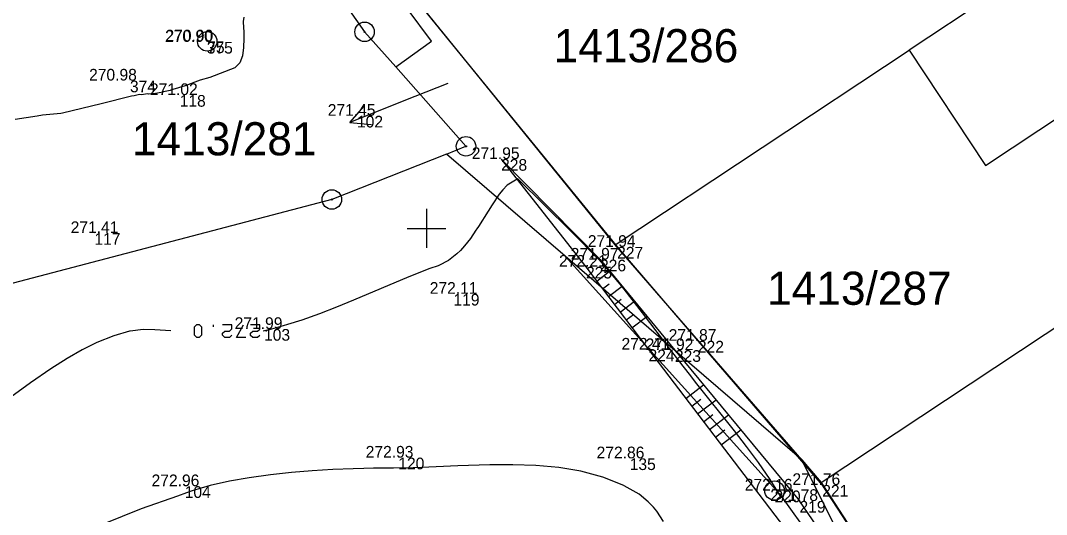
# Model space of a CAD drawing. Extents: x -771260 to -770828, y -1053564 to -1052811.
# Drawn here: x -770970.9 to -770918.2, y -1053264.7 to -1053239.3 of the extents above; entities that cross this region are included whole.
import ezdxf

# ---------------------------------------------------------------- set-up
doc = ezdxf.new("R2010")
doc.units = 0
for name, color, linetype in [('14_8_2023_krizky', 7, 'Continuous'), ('18_8_2023_plot', 7, 'Continuous'), ('18_8_2023_sachta', 7, 'Continuous'), ('18_8_2023_ter_hrana', 7, 'Continuous'), ('18_8_2023_ter_pata', 7, 'Continuous'), ('18_8_2023_ter_srafa', 7, 'Continuous'), ('18_8_2023_vrstevnice_po_1m', 7, 'Continuous'), ('18_8_2023_zamereny_bod', 7, 'Continuous'), ('18_8_2023_zamereny_bod_cislo', 7, 'Continuous'), ('18_8_2023_zamereny_bod_vyska', 7, 'Continuous'), ('25_3_2019_krizky_JTSK', 7, 'Continuous'), ('25_3_2019_sachta', 7, 'Continuous'), ('25_3_2019_vrstevnice_interval_po_1m', 7, 'Continuous'), ('25_3_2019_zamereny_bod', 7, 'Continuous'), ('25_3_2019_zamereny_bod_cislo', 7, 'Continuous'), ('25_3_2019_zamereny_bod_vyska', 7, 'Continuous'), ('Default', 7, 'Continuous'), ('DKM_Hranice parcel', 7, 'Continuous'), ('DKM_Parcelní čísla', 7, 'Continuous'), ('DKM_Pop  PČ popisy', 7, 'Continuous'), ('DKM_Značky bodu BP', 7, 'Continuous')]:
    doc.layers.add(name, color=color, linetype=linetype)

# ---------------------------------------------------------------- blocks, each defined once
blk = doc.blocks.new('6.200_1')
at = {"layer": '25_3_2019_sachta'}
blk.add_circle((0, 0), 10, dxfattribs=at)
blk = doc.blocks.new('POINT_DISPLAY')
at = {"layer": 'Default'}
blk.add_line((0, 0), (0, 0), dxfattribs=at)
blk = doc.blocks.new('KRIZEK')
at = {"layer": '25_3_2019_krizky_JTSK'}
for p, q in [((0, 10), (0, -10)), ((-10, 0), (10, 0))]:
    blk.add_line(p, q, dxfattribs=at)

msp = doc.modelspace()

# ---------------------------------------------------------------- linework, layer by layer
at = {"layer": '18_8_2023_plot'}
for p, q in [((-770950.474, -1053238.36), (-770940.208, -1053250.948)), ((-770940.208, -1053250.948), (-770936.059, -1053255.767)), ((-770936.059, -1053255.767), (-770929.672, -1053263.164)), ((-770929.672, -1053263.164), (-770925.377, -1053269.752))]:
    msp.add_line(p, q, dxfattribs=at)
at = {"layer": '18_8_2023_sachta'}
msp.add_circle((-770932.123, -1053263.449), 0.5, dxfattribs=at)
at = {"layer": '18_8_2023_ter_hrana'}
for p, q in [((-770946.168, -1053246.443), (-770941.807, -1053251.969)), ((-770941.807, -1053251.969), (-770938.594, -1053256.22)), ((-770938.594, -1053256.22), (-770931.61, -1053265.367))]:
    msp.add_line(p, q, dxfattribs=at)
at = {"layer": '18_8_2023_ter_pata'}
for p, q in [((-770946.168, -1053246.443), (-770941.087, -1053251.604)), ((-770941.087, -1053251.604), (-770937.24, -1053256.247)), ((-770937.24, -1053256.247), (-770930.841, -1053263.982)), ((-770926.437, -1053270.365), (-770930.841, -1053263.982))]:
    msp.add_line(p, q, dxfattribs=at)
at = {"layer": '18_8_2023_ter_srafa'}
for p, q in [((-770941.254, -1053252.7), (-770940.593, -1053252.2)), ((-770940.952, -1053253.099), (-770940.613, -1053252.842)), ((-770940.651, -1053253.497), (-770939.954, -1053252.971)), ((-770940.349, -1053253.896), (-770939.992, -1053253.626)), ((-770940.048, -1053254.295), (-770939.315, -1053253.741)), ((-770939.746, -1053254.694), (-770939.371, -1053254.41)), ((-770939.445, -1053255.093), (-770938.677, -1053254.512)), ((-770936.68, -1053258.726), (-770935.766, -1053258.028)), ((-770936.376, -1053259.123), (-770935.912, -1053258.768)), ((-770936.073, -1053259.521), (-770935.128, -1053258.799)), ((-770935.77, -1053259.918), (-770935.289, -1053259.551)), ((-770935.466, -1053260.315), (-770934.49, -1053259.57)), ((-770935.163, -1053260.713), (-770934.667, -1053260.334)), ((-770934.859, -1053261.11), (-770933.852, -1053260.341))]:
    msp.add_line(p, q, dxfattribs=at)
at = {"layer": '18_8_2023_vrstevnice_po_1m'}
for points in [[(-770931.787, -1053263.783), (-770932.354, -1053262.878), (-770932.945, -1053262.017), (-770933.555, -1053261.189), (-770934.177, -1053260.384), (-770936.18, -1053257.881), (-770936.422, -1053257.572), (-770936.814, -1053257.07), (-770937.443, -1053256.243), (-770938.896, -1053254.331), (-770939.973, -1053252.963), (-770940.907, -1053251.847), (-770941.026, -1053251.717), (-770941.116, -1053251.619), (-770941.126, -1053251.607), (-770942.592, -1053250.135), (-770945.311, -1053247.458), (-770945.349, -1053247.481), (-770945.848, -1053247.778), (-770946.073, -1053248.015), (-770946.267, -1053248.249), (-770946.629, -1053248.792), (-770946.823, -1053249.116), (-770947.329, -1053249.907), (-770947.416, -1053250.024), (-770947.458, -1053250.087), (-770947.743, -1053250.518), (-770948.044, -1053250.892), (-770948.256, -1053251.129), (-770948.441, -1053251.303), (-770948.872, -1053251.651), (-770949.357, -1053251.9), (-770949.398, -1053251.914), (-770949.821, -1053252.062), (-770950.898, -1053252.48), (-770953.742, -1053253.685), (-770954.618, -1053254.044), (-770955.503, -1053254.387), (-770956.4, -1053254.707), (-770957.14, -1053254.938), (-770957.36, -1053255.006), (-770958.203, -1053255.234), (-770958.256, -1053255.245), (-770958.386, -1053255.273)], [(-770945.848, -1053247.778), (-770945.848, -1053247.778)], [(-770945.311, -1053247.458), (-770945.311, -1053247.458)], [(-770946.267, -1053248.249), (-770946.267, -1053248.249)], [(-770946.073, -1053248.015), (-770946.073, -1053248.015)], [(-770946.629, -1053248.792), (-770946.629, -1053248.792)], [(-770946.823, -1053249.116), (-770946.823, -1053249.116)], [(-770947.329, -1053249.907), (-770947.329, -1053249.907)], [(-770947.416, -1053250.024), (-770947.416, -1053250.024)], [(-770942.592, -1053250.135), (-770942.592, -1053250.135)], [(-770948.044, -1053250.892), (-770948.044, -1053250.892)], [(-770947.743, -1053250.518), (-770947.743, -1053250.518)], [(-770948.441, -1053251.303), (-770948.441, -1053251.303)], [(-770948.256, -1053251.129), (-770948.256, -1053251.129)], [(-770949.357, -1053251.9), (-770949.357, -1053251.9)], [(-770948.872, -1053251.651), (-770948.872, -1053251.651)], [(-770941.126, -1053251.607), (-770941.126, -1053251.607)], [(-770940.907, -1053251.847), (-770940.907, -1053251.847)], [(-770950.898, -1053252.48), (-770950.898, -1053252.48)], [(-770949.821, -1053252.062), (-770949.821, -1053252.062)], [(-770939.973, -1053252.963), (-770939.973, -1053252.963)], [(-770954.618, -1053254.044), (-770954.618, -1053254.044)], [(-770953.742, -1053253.685), (-770953.742, -1053253.685)], [(-770955.503, -1053254.387), (-770955.503, -1053254.387)], [(-770938.896, -1053254.331), (-770938.896, -1053254.331)], [(-770961.677, -1053254.937), (-770961.558, -1053255.047), (-770961.559, -1053255.482), (-770961.679, -1053255.59), (-770961.799, -1053255.59), (-770961.918, -1053255.481), (-770961.917, -1053255.046), (-770961.797, -1053254.937), (-770961.677, -1053254.937)], [(-770960.959, -1053254.939), (-770960.959, -1053255.048)], [(-770960.003, -1053255.486), (-770960.123, -1053255.595), (-770960.362, -1053255.594), (-770960.481, -1053255.485), (-770960.481, -1053255.376), (-770960.361, -1053255.267), (-770960.122, -1053255.268), (-770960.002, -1053255.16), (-770960.001, -1053254.942), (-770960.48, -1053254.941)], [(-770959.285, -1053255.597), (-770959.763, -1053255.595), (-770959.403, -1053254.943)], [(-770958.566, -1053255.49), (-770958.686, -1053255.598), (-770958.925, -1053255.598), (-770959.045, -1053255.489), (-770959.045, -1053255.38), (-770958.925, -1053255.271), (-770958.685, -1053255.272), (-770958.565, -1053255.163), (-770958.565, -1053254.946), (-770959.043, -1053254.944)], [(-770957.36, -1053255.006), (-770957.36, -1053255.006)], [(-770956.4, -1053254.707), (-770956.4, -1053254.707)], [(-770963.135, -1053255.26), (-770963.951, -1053255.204), (-770964.551, -1053255.191), (-770965.22, -1053255.265), (-770965.259, -1053255.276), (-770966.067, -1053255.505), (-770966.931, -1053255.855), (-770967.677, -1053256.223), (-770968.452, -1053256.667), (-770969.289, -1053257.202), (-770970.335, -1053257.926), (-770972.195, -1053259.25), (-770972.396, -1053259.385), (-770972.441, -1053259.413), (-770972.912, -1053259.698), (-770972.947, -1053259.722), (-770973.349, -1053259.992), (-770973.605, -1053260.15), (-770974.329, -1053260.642)], [(-770966.067, -1053255.505), (-770966.067, -1053255.505)], [(-770965.22, -1053255.265), (-770965.22, -1053255.265)], [(-770964.551, -1053255.191), (-770964.551, -1053255.191)], [(-770963.951, -1053255.204), (-770963.951, -1053255.204)], [(-770963.135, -1053255.26), (-770963.135, -1053255.26)], [(-770958.203, -1053255.234), (-770958.203, -1053255.234)], [(-770967.677, -1053256.223), (-770967.677, -1053256.223)], [(-770966.931, -1053255.855), (-770966.931, -1053255.855)], [(-770968.452, -1053256.667), (-770968.452, -1053256.667)], [(-770969.289, -1053257.202), (-770969.289, -1053257.202)], [(-770936.814, -1053257.07), (-770936.814, -1053257.07)], [(-770970.335, -1053257.926), (-770970.335, -1053257.926)], [(-770936.18, -1053257.881), (-770936.18, -1053257.881)], [(-770934.177, -1053260.384), (-770934.177, -1053260.384)], [(-770933.555, -1053261.189), (-770933.555, -1053261.189)], [(-770932.945, -1053262.017), (-770932.945, -1053262.017)], [(-770937.818, -1053265.034), (-770938.172, -1053264.514), (-770938.341, -1053264.296), (-770938.618, -1053264.028), (-770939.069, -1053263.633), (-770939.847, -1053263.198), (-770939.869, -1053263.19), (-770940.941, -1053262.764), (-770942.067, -1053262.462), (-770943.21, -1053262.267), (-770944.376, -1053262.162), (-770945.557, -1053262.123), (-770946.748, -1053262.131), (-770948.381, -1053262.188), (-770950.608, -1053262.285), (-770950.685, -1053262.286), (-770951.699, -1053262.297), (-770951.714, -1053262.297), (-770951.935, -1053262.304), (-770952.726, -1053262.302), (-770953.209, -1053262.319), (-770953.763, -1053262.327), (-770954.809, -1053262.372), (-770955.866, -1053262.436), (-770956.933, -1053262.523), (-770958.014, -1053262.638), (-770959.113, -1053262.788), (-770960.111, -1053262.961), (-770961.108, -1053263.182), (-770962.032, -1053263.457), (-770962.082, -1053263.475), (-770962.326, -1053263.564), (-770962.783, -1053263.731), (-770962.793, -1053263.735), (-770964.655, -1053264.394), (-770966.609, -1053265.169)], [(-770956.933, -1053262.523), (-770956.933, -1053262.523)], [(-770955.866, -1053262.436), (-770955.866, -1053262.436)], [(-770954.809, -1053262.372), (-770954.809, -1053262.372)], [(-770953.763, -1053262.327), (-770953.763, -1053262.327)], [(-770953.209, -1053262.319), (-770953.209, -1053262.319)], [(-770952.726, -1053262.302), (-770952.726, -1053262.302)], [(-770951.935, -1053262.304), (-770951.935, -1053262.304)], [(-770951.699, -1053262.297), (-770951.699, -1053262.297)], [(-770950.608, -1053262.285), (-770950.608, -1053262.285)], [(-770948.381, -1053262.188), (-770948.381, -1053262.188)], [(-770946.748, -1053262.131), (-770946.748, -1053262.131)], [(-770945.557, -1053262.123), (-770945.557, -1053262.123)], [(-770944.376, -1053262.162), (-770944.376, -1053262.162)], [(-770943.21, -1053262.267), (-770943.21, -1053262.267)], [(-770942.067, -1053262.462), (-770942.067, -1053262.462)], [(-770960.111, -1053262.961), (-770960.111, -1053262.961)], [(-770959.113, -1053262.788), (-770959.113, -1053262.788)], [(-770958.014, -1053262.638), (-770958.014, -1053262.638)], [(-770940.941, -1053262.764), (-770940.941, -1053262.764)], [(-770932.354, -1053262.878), (-770932.354, -1053262.878)], [(-770962.032, -1053263.457), (-770962.032, -1053263.457)], [(-770961.108, -1053263.182), (-770961.108, -1053263.182)], [(-770939.847, -1053263.198), (-770939.847, -1053263.198)], [(-770962.783, -1053263.731), (-770962.783, -1053263.731)], [(-770939.069, -1053263.633), (-770939.069, -1053263.633)], [(-770938.618, -1053264.028), (-770938.618, -1053264.028)], [(-770931.787, -1053263.783), (-770931.787, -1053263.783)], [(-770964.655, -1053264.394), (-770964.655, -1053264.394)], [(-770938.341, -1053264.296), (-770938.341, -1053264.296)], [(-770938.172, -1053264.514), (-770938.172, -1053264.514)]]:
    msp.add_lwpolyline(points, dxfattribs=at)
at = {"layer": '18_8_2023_zamereny_bod'}
for p, q in [((-770962.677, -1053243.16), (-770962.677, -1053243.16)), ((-770953.57, -1053244.225), (-770953.57, -1053244.225)), ((-770946.168, -1053246.443), (-770946.168, -1053246.443)), ((-770967.058, -1053250.241), (-770967.058, -1053250.241)), ((-770940.208, -1053250.948), (-770940.208, -1053250.948)), ((-770941.807, -1053251.969), (-770941.807, -1053251.969)), ((-770941.087, -1053251.604), (-770941.087, -1053251.604)), ((-770948.615, -1053253.357), (-770948.615, -1053253.357)), ((-770958.344, -1053255.161), (-770958.344, -1053255.161)), ((-770938.594, -1053256.22), (-770938.594, -1053256.22)), ((-770936.059, -1053255.767), (-770936.059, -1053255.767)), ((-770937.24, -1053256.247), (-770937.24, -1053256.247)), ((-770951.448, -1053261.76), (-770951.448, -1053261.76)), ((-770939.562, -1053261.796), (-770939.562, -1053261.796)), ((-770962.418, -1053263.226), (-770962.418, -1053263.226)), ((-770932.123, -1053263.449), (-770932.123, -1053263.449)), ((-770929.672, -1053263.164), (-770929.672, -1053263.164)), ((-770930.841, -1053263.982), (-770930.841, -1053263.982))]:
    msp.add_line(p, q, dxfattribs=at)
at = {"layer": '25_3_2019_vrstevnice_interval_po_1m'}
for points in [[(-770959.374, -1053239.171), (-770959.409, -1053239.395), (-770959.408, -1053239.414), (-770959.383, -1053239.943), (-770959.379, -1053240.254), (-770959.399, -1053240.718), (-770959.453, -1053241.148), (-770959.58, -1053241.51), (-770959.828, -1053241.755), (-770959.848, -1053241.763), (-770961.12, -1053242.261), (-770961.627, -1053242.4), (-770961.628, -1053242.4), (-770962.4, -1053242.687), (-770962.691, -1053242.777), (-770962.784, -1053242.814), (-770963.096, -1053242.894), (-770963.163, -1053242.92), (-770963.503, -1053242.992), (-770963.539, -1053243.006), (-770963.918, -1053243.078), (-770964.278, -1053243.107), (-770964.326, -1053243.1), (-770964.644, -1053243.141), (-770964.739, -1053243.137), (-770965.015, -1053243.201), (-770965.147, -1053243.22), (-770965.154, -1053243.222), (-770966.714, -1053243.612), (-770968.695, -1053244.082), (-770968.773, -1053244.1), (-770969.725, -1053244.196), (-770969.99, -1053244.244), (-770971.13, -1053244.409)], [(-770959.409, -1053239.395), (-770959.409, -1053239.395)], [(-770959.383, -1053239.943), (-770959.383, -1053239.943)], [(-770959.379, -1053240.254), (-770959.379, -1053240.254)], [(-770959.399, -1053240.718), (-770959.399, -1053240.718)], [(-770959.453, -1053241.148), (-770959.453, -1053241.148)], [(-770959.828, -1053241.755), (-770959.828, -1053241.755)], [(-770959.58, -1053241.51), (-770959.58, -1053241.51)], [(-770961.627, -1053242.4), (-770961.627, -1053242.4)], [(-770961.12, -1053242.261), (-770961.12, -1053242.261)], [(-770963.539, -1053243.006), (-770963.539, -1053243.006)], [(-770963.503, -1053242.992), (-770963.503, -1053242.992)], [(-770963.163, -1053242.92), (-770963.163, -1053242.92)], [(-770963.096, -1053242.894), (-770963.096, -1053242.894)], [(-770962.784, -1053242.814), (-770962.784, -1053242.814)], [(-770962.691, -1053242.777), (-770962.691, -1053242.777)], [(-770962.4, -1053242.687), (-770962.4, -1053242.687)], [(-770965.147, -1053243.22), (-770965.147, -1053243.22)], [(-770965.015, -1053243.201), (-770965.015, -1053243.201)], [(-770964.739, -1053243.137), (-770964.739, -1053243.137)], [(-770964.644, -1053243.141), (-770964.644, -1053243.141)], [(-770964.326, -1053243.1), (-770964.326, -1053243.1)], [(-770964.278, -1053243.107), (-770964.278, -1053243.107)], [(-770963.918, -1053243.078), (-770963.918, -1053243.078)], [(-770968.773, -1053244.1), (-770968.773, -1053244.1)], [(-770966.714, -1053243.612), (-770966.714, -1053243.612)], [(-770969.99, -1053244.244), (-770969.99, -1053244.244)], [(-770969.725, -1053244.196), (-770969.725, -1053244.196)]]:
    msp.add_lwpolyline(points, dxfattribs=at)
at = {"layer": 'DKM_Hranice parcel'}
for p, q in [((-770913.81, -1053233.33), (-770925.2, -1053240.85)), ((-770940.3, -1053250.84), (-770925.2, -1053240.85)), ((-770942.88, -1053251.43), (-770948.98, -1053246.19)), ((-770930.72, -1053261.88), (-770940.3, -1053250.84)), ((-770930.72, -1053261.88), (-770942.88, -1053251.43)), ((-770929.73, -1053263.03), (-770916.38, -1053254.2)), ((-770930.72, -1053261.88), (-770929.73, -1053263.03))]:
    msp.add_line(p, q, dxfattribs=at)
for points in [[(-770974.57, -1053209.54), (-770953.18, -1053239.92), (-770951.58, -1053241.72)], [(-770951.58, -1053241.72), (-770949.74, -1053240.39), (-770950.99, -1053238.72)], [(-770940.3, -1053250.84), (-770950.33, -1053238.52), (-770950.44, -1053238.36)], [(-770925.2, -1053240.85), (-770921.28, -1053246.78), (-770914.44, -1053242.25), (-770913.4, -1053243.84), (-770913.48, -1053243.89), (-770910.34, -1053248.65), (-770905.71, -1053245.59), (-770904.99, -1053246.67)], [(-770948.98, -1053246.19), (-770947.97, -1053245.79), (-770951.58, -1053241.72)], [(-770948.98, -1053246.19), (-770954.86, -1053248.52), (-770990.42, -1053257.84), (-771009.33, -1053262.49)], [(-770942.88, -1053251.43), (-770931.86, -1053263.62), (-770929.04, -1053267.55)], [(-770909.23, -1053307.52), (-770910.75, -1053304.08), (-770920.71, -1053281.89), (-770930.72, -1053261.88)], [(-770929.73, -1053263.03), (-770929.66, -1053263.13), (-770921.01, -1053276.44)]]:
    msp.add_lwpolyline(points, dxfattribs=at)
at = {"layer": 'DKM_Pop  PČ popisy'}
for p, q in [((-770948.91, -1053242.56), (-770951.16, -1053243.45)), ((-770951.16, -1053243.45), (-770953.942, -1053244.574)), ((-770953.942, -1053244.574), (-770953.202, -1053243.735)), ((-770953.942, -1053244.574), (-770952.826, -1053244.663))]:
    msp.add_line(p, q, dxfattribs=at)
at = {"layer": 'DKM_Značky bodu BP'}
for centre, radius in [((-770953.18, -1053239.92), 0.5), ((-770953.18, -1053239.92), 0.0303), ((-770947.97, -1053245.79), 0.5), ((-770947.97, -1053245.79), 0.0303), ((-770954.86, -1053248.52), 0.5), ((-770954.86, -1053248.52), 0.0303)]:
    msp.add_circle(centre, radius, dxfattribs=at)

# ---------------------------------------------------------------- block references
at = {"layer": '14_8_2023_krizky', "xscale": 0.1, "yscale": 0.10000000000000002}
msp.add_blockref('KRIZEK', (-770950, -1053250), dxfattribs=at)
at = {"layer": '25_3_2019_sachta', "xscale": 0.05, "yscale": 0.05000000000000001}
msp.add_blockref('6.200_1', (-770961.261, -1053240.409), dxfattribs=at)
at = {"layer": '25_3_2019_zamereny_bod', "xscale": 0.1, "yscale": 0.10000000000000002}
for p in [(-770961.261, -1053240.409), (-770961.286, -1053240.433), (-770965.232, -1053242.418)]:
    msp.add_blockref('POINT_DISPLAY', p, dxfattribs=at)

# ---------------------------------------------------------------- texts
at = {"layer": '18_8_2023_zamereny_bod_cislo'}
for s, p in [('118', (-770962.677, -1053243.76)), ('102', (-770953.57, -1053244.825)), ('228', (-770946.168, -1053247.043)), ('117', (-770967.058, -1053250.841)), ('227', (-770940.208, -1053251.548)), ('225', (-770941.807, -1053252.569)), ('226', (-770941.087, -1053252.204)), ('119', (-770948.615, -1053253.957)), ('103', (-770958.344, -1053255.761)), ('224', (-770938.594, -1053256.82)), ('222', (-770936.059, -1053256.367)), ('223', (-770937.24, -1053256.847)), ('120', (-770951.448, -1053262.36)), ('135', (-770939.562, -1053262.396)), ('104', (-770962.418, -1053263.826)), ('220', (-770932.123, -1053264.049)), ('221', (-770929.672, -1053263.764)), ('219', (-770930.841, -1053264.582))]:
    msp.add_text(s, height=0.6, dxfattribs=at).set_placement(p)
at = {"layer": '18_8_2023_zamereny_bod_vyska'}
for s, p in [('271.02 ', (-770964.205, -1053243.16)), ('271.45 ', (-770955.072, -1053244.225)), ('271.95 ', (-770947.672, -1053246.443)), ('271.41 ', (-770968.276, -1053250.241)), ('271.94 ', (-770941.712, -1053250.948)), ('272.21 ', (-770943.195, -1053251.969)), ('271.97 ', (-770942.591, -1053251.604)), ('272.11 ', (-770949.833, -1053253.357)), ('271.99 ', (-770959.852, -1053255.161)), ('271.87 ', (-770937.561, -1053255.767)), ('272.41 ', (-770939.982, -1053256.22)), ('271.92 ', (-770938.744, -1053256.247)), ('272.93 ', (-770953.122, -1053261.76)), ('272.86 ', (-770941.262, -1053261.796)), ('271.76 ', (-770931.202, -1053263.164)), ('272.96 ', (-770964.12, -1053263.226)), ('272.16 ', (-770933.653, -1053263.449)), ('271.78 ', (-770932.343, -1053263.982))]:
    msp.add_text(s, height=0.6, dxfattribs=at).set_placement(p)
at = {"layer": '25_3_2019_zamereny_bod_cislo'}
for s, p in [('375', (-770961.286, -1053241.033)), ('75', (-770961.261, -1053241.009)), ('374', (-770965.232, -1053243.018))]:
    msp.add_text(s, height=0.6, dxfattribs=at).set_placement(p)
at = {"layer": '25_3_2019_zamereny_bod_vyska'}
for s, p in [('270.90 ', (-770963.43, -1053240.433)), ('270.90 ', (-770963.405, -1053240.409)), ('270.98 ', (-770967.33, -1053242.418))]:
    msp.add_text(s, height=0.6, dxfattribs=at).set_placement(p)
at = {"layer": 'DKM_Parcelní čísla'}
for s, p in [('1413/286', (-770943.465, -1053241.479)), ('1413/281', (-770965.131, -1053246.254)), ('1413/287', (-770932.505, -1053253.92))]:
    msp.add_text(s, height=1.7, dxfattribs=at).set_placement(p)

doc.saveas('drawing.dxf')
